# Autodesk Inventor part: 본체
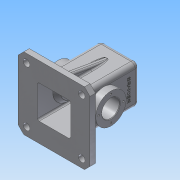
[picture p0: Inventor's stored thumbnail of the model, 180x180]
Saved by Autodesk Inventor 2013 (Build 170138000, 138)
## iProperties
Created: 2016-02
Part Number: 본체
Material: 알루미늄 6061
Document SubType Name: Modeling
Designer: Administrator
Density: 2.71 g/cm^3
Mass: 931.555 g
Surface Area: 1047.27 cm^2
Volume: 343.747 cm^3
Author: Administrator
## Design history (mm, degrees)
sketch "스케치3"
  geometry: L1 (-35, 35)-(35, 35); L2 (35, 35)-(35, -35); L3 (35, -35)-(-35, -35); L4 (-35, -35)-(-35, 35); L5 (-35, 35)-(35, -35); L6 (35, 35)-(-35, -35); 1 further point
  constraints: 12 end point, 2 midpoint, 2 parallel, 1 horizontal, 1 perpendicular
  dimensions: "d4" = 70 distance of L2.end L3.end; "d5" = 70 distance of L1.end L2.end
extrude "돌출2" new body sketch "스케치3" distance "d6" = 120; taper "d7" = 0 deg
feature "쉘2" dims "d8" = 5
sketch "스케치4"
  geometry: L1 (35, 35)-(-35, 35) reference; L2 (-35, 35)-(-35, -35) reference; L3 (-35, -35)-(35, -35) reference; L4 (35, -35)-(35, 35) reference; L5 (65, -65)-(-65, -65); L6 (-65, -65)-(-65, 65); L7 (-65, 65)-(65, 65); L8 (65, 65)-(65, -65); L9 (65, -65)-(-65, 65); L10 (-65, -65)-(65, 65); 1 further point
  constraints: 12 end point, 2 midpoint, 2 parallel, 1 horizontal, 1 perpendicular
  dimensions: "d9" = 130 distance of L6.end L7.end; "d10" = 130 distance of L5.end L6.end
extrude "돌출3" join sketch "스케치4" distance "d11" = 10; taper "d12" = 0 deg
sketch "스케치5"
  geometry: C1 r 20 at (0, 0); 1 further point
  constraints: 1 centre point, 1 coincident
  dimensions: "d13" = 40 diameter of C1
extrude "돌출4" join sketch "스케치5" distance "d14" = 10; taper "d15" = -10 deg
hole "구멍1" diameter "d18" = 21; stored, may be unused: countersink angle "d22" = 90 deg, drill point angle "d24" = 118 deg; dims "d16" = 10, "d17" = 10, "d19" = 6, "d20" = 28, "d21" = 4, "d23" = 8
sketch "스케치6"
  geometry: L1 (70, 0)-(0, 0) reference; L2 (-30, -120)-(100, -120) reference; C1 r 27.5 at (35, -65); 2 further points
  constraints: 1 centre point, 1 midpoint, 1 vertical alignment
  dimensions: "d25" = 55 diameter of C1; "d27" = 55 distance from line of C1.centre L2
extrude "돌출6" join sketch "스케치6" distance "d30" = 13; taper "d31" = 0 deg
sketch "스케치8"
  geometry: L1 (65, 120)-(65, 10) reference; C1 r 27.5 at (30, 55) reference; C2 r 27.5 at (30, 55); 1 further point
  constraints: 1 centre point, 1 coincident
  dimensions: "d32" = 55 diameter of C2
extrude "돌출7" join sketch "스케치8" distance "d33" = 7; taper "d34" = -45 deg
sketch "스케치9"
  geometry: C1 r 27.5 at (0, 0) reference; C2 r 16 at (0, 0); 1 further point
  constraints: 1 centre point, 1 coincident
  dimensions: "d35" = 32 diameter of C2
extrude "돌출8" cut sketch "스케치9" stored distance "d36" = 7; taper "d37" = 0 deg
sketch "스케치10"
  geometry: C1 r 16 at (0, 0) reference; 2 further points
  constraints: 1 vertical alignment
  dimensions: "d38" = 22.5 distance of C1.centre point (0, 22.5)
hole "구멍2" sketch "스케치10" at (0, 22.5) diameter "d39" = 3.242; stored, may be unused: countersink angle "d43" = 90 deg, drill point angle "d45" = 118 deg; dims "d40" = 8, "d41" = 28, "d42" = 4, "d44" = 10
sketch "스케치11"
  geometry: L1 (-110, -50)-(-24.931, -35); L2 (-120, -30)-(-5, -30) reference; L3 (-5, -30)-(-5, -10.5) reference; L4 (-5, -10.5)-(6, -10.5) reference; L5 (6, -10.5)-(6, -14) reference; L6 (6, -14)-(10, -14) reference; L7 (10, -14)-(10, -18.237) reference; L8 (10, -18.237)-(0, -20) reference; L9 (0, -20)-(0, -35) reference; L10 (0, -35)-(-110, -35) reference; L11 (-110, -35)-(-110, -65) reference; L12 (-110, -65)-(-120, -65) reference; L13 (-120, -65)-(-120, -30) reference; L14 (-5, 30)-(-120, 30) reference; L15 (-120, 30)-(-120, 65) reference; L16 (-120, 65)-(-110, 65) reference; L17 (-110, 65)-(-110, 35) reference; L18 (-110, 35)-(0, 35) reference; L19 (0, 35)-(0, 20) reference; L20 (0, 20)-(10, 18.237) reference; L21 (10, 18.237)-(10, 14) reference; L22 (10, 14)-(6, 14) reference; L23 (6, 14)-(6, 10.5) reference; L24 (6, 10.5)-(-5, 10.5) reference; L25 (-5, 10.5)-(-5, 30) reference; 1 further point
  constraints: 2 end point, 1 midpoint, 1 point on line
  dimensions: "d49" = 15 distance from line of L1.start L12; "d52" = 10 deg angle of L1 L12
extrude "돌출9" join sketch "스케치11" stored distance "d53" = 10; taper "d54" = 0 deg
sketch "스케치12"
  geometry: L1 (65, 65)-(-65, 65) reference; L2 (65, -65)-(65, 65) reference; C1 r 6 at (50, 50); 1 further point
  constraints: 1 centre point
  dimensions: "d55" = 12 diameter of C1; "d57" = 15 distance from line of L2 C1.centre; "d58" = 15 distance from line of C1.centre L1
extrude "돌출10" cut sketch "스케치12" stored distance "d59" = 10; taper "d60" = 0 deg
chamfer "모따기1" distance "d64" = 10; stored, may be unused: second distance "d65" = 2, angle "d66" = 45 deg
chamfer "모따기2" distance "d67" = 1; stored, may be unused: second distance "d68" = 2, angle "d69" = 45 deg
fillet "모깎기1" dims "d70" = 8, "d71" = 3, "d72" = 0.5
fillet "모깎기2" dims "d73" = 0.5
fillet "모깎기3" dims "d74" = 3
fillet "모깎기4" dims "d75" = 3
fillet "모깎기5" dims "d76" = 8
sketch "스케치13"
  geometry: L1 (34.55, -45)-(65, -45) reference; L2 (65, -45)-(65, -55) reference; L3 (65, -55)-(-65, -55) reference; L4 (-65, -55)-(-65, -45) reference; L5 (-65, -45)-(-34.55, -45) reference; L6 (27, -42)-(-27, -42) reference; L7 (27, -5.22)-(27, -42) reference; L8 (-27, -5.22)-(-27, -42) reference; L9 (27, 57)-(27, 5.22) reference; L10 (27, 57)-(-27, 57) reference; L11 (-27, 57)-(-27, 5.22) reference; L12 (-18.237, 75)-(18.237, 75) reference; C1 r 16 at (0, 0) reference; A1 r 27.5 centre (0, 0) between (27, 5.22) and (-27, 5.22) reference; A2 r 27.5 centre (0, 0) between (-27, -5.22) and (27, -5.22) reference; A3 r 27.5 centre (0, 0) between (27, -5.22) and (27, 5.22) reference; A4 r 27.5 centre (0, 0) between (27, 5.22) and (-27, 5.22) reference; A5 r 27.5 centre (0, 0) between (-27, 5.22) and (-27, -5.22) reference; 2 further points
  constraints: 1 vertical alignment, 3 other
  dimensions: "d77" = 30 distance from line of L12 point (0, 45)
feature "엠보싱1" sketch "스케치13" dims "d4" = 70, "d5" = 70, "d10" = 130, "d78" = 0.5, "d79" = 0
fillet "모깎기6" dims "d80" = 3
fillet "모깎기7" dims "d81" = 3
node "솔리드2"
mirror "대칭2"
pattern_circular "원형 패턴1" dims angle "d47" = 360 deg
mirror "대칭3"
mirror "대칭4"
pattern_circular "원형 패턴2" dims angle "d62" = 360 deg
node "절단 모서리 투영1"
node "절단 모서리 투영2"
